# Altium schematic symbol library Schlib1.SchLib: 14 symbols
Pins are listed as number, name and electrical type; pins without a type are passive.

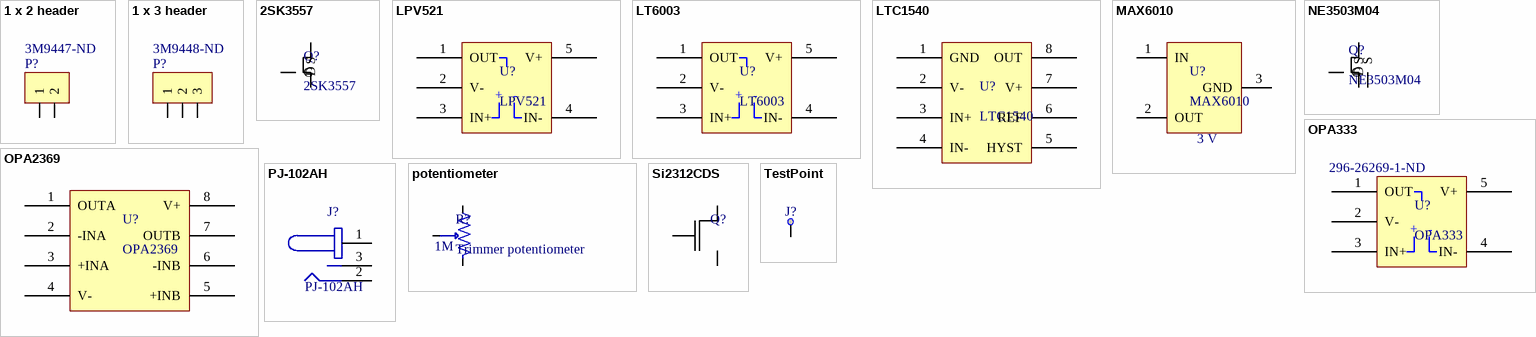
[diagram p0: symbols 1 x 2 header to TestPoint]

## 1 x 2 header
designator P?  Supplier Part Number 1: 3M9447-ND  (hidden comment: 1 x 2 header)
100 mils standard header
footprint 1x2 header (1x2 header, 100 mils)
pins: 1, 2

## 1 x 3 header
designator P?  Supplier Part Number 1: 3M9448-ND  (hidden comment: 1 x 3 header)
100 mils standard header
footprint 1x3 header (1x3 header, 100 mils)
pins: 1, 2, 3

## 2SK3557
designator Q?
N-Channel JFET
footprint SOT23-3N (SOT23, 3-Leads, Body 2.9x1.3mm, Pitch 0.95mm, Lead Span 2.5mm, IPC Medium Density)
pins: 1 S, 2 D, 3 G

## LPV521
designator U?
Nanopower, 1.8V, RRIO, CMOS Input, Operational Amplifier
footprint SC70-5
pins: 1 OUT, 2 V-, 3 IN+, 4 IN-, 5 V+

## LT6003
designator U?
1.6V, 1µA Precision   Rail-to-Rail Input and   Output Op Amps
footprint TSOT23-5 (SOT23, 5-Leads, Body 2.90x2.80mm, Pitch 0.95mm, IPC Medium Density)
pins: 1 OUT, 2 V-, 3 IN+, 4 IN-, 5 V+

## LTC1540
designator U?
Nanopower Comparator  with Reference
footprint SOIC-8 (SOIC, 8-Leads, Body 5.10x3.91mm, Pitch 1.27mm, IPC Medium Density)
pins: 1 GND, 2 V-, 3 IN+, 4 IN-, 5 HYST, 6 REF, 7 V+, 8 OUT

## MAX6010
designator U?  value 3 V
Precision Micropower Shunt Voltage Reference
footprint SOT23-3N (SOT23, 3-Leads, Body 2.9x1.3mm, Pitch 0.95mm, Lead Span 2.5mm, IPC Medium Density)
pins: 1 IN, 2 OUT, 3 GND

## NE3503M04
designator Q?
C TO Ku BAND SUPER LOW NOISE AND HIGH-GAIN AMPLIFIER   N-CHANNEL HJ-FET
footprint M04 (FLAT-LEAD 4-PIN THIN-TYPE SUPER MINIMOLD (M04))
pins: 1 S, 2 D, 3 S, 4 G

## OPA333
designator U?  Supplier Part Number 1: 296-26269-1-ND
1.8V, microPOWER  CMOS OPERATIONAL AMPLIFIERS  Zerø-Drift Series
footprint SOT23-5 (SOT23, 5-Leads, Body 2.9x1.6mm, Pitch 0.95mm, Lead Span 2.8mm, IPC High Density)
pins: 1 OUT, 2 V-, 3 IN+, 4 IN-, 5 V+

## OPA2369
designator U?
1.8V, 700nA, Zerø-Crossover  RAIL-TO-RAIL I/O OPERATIONAL AMPLIFIER
footprint MSOP-8 (TSOP, 8-Leads, Body 3.00x3.00mm, Pitch 0.65mm, IPC Medium Density)
pins: 1 OUTA, 2 -INA, 3 +INA, 4 V-, 5 +INB, 6 -INB, 7 OUTB, 8 V+

## PJ-102AH
designator J?
CONN PWR JACK 2.1X5.5MM HIGH CUR
footprint PJ-102AH (Power Jack)
pins: 1, 2, 3

## potentiometer
designator R?, comment Trimmer potentiometer  value 1M
footprint 3386P (trimming pot)
footprint 3296Y (Bourns 3296Y trimmer)
pins: 1, 2, 3

## Si2312CDS
designator Q?  (value not drawn)
N-Channel 20 V (D-S) MOSFET
footprint SOT23-3N (SOT23, 3-Leads, Body 2.9x1.3mm, Pitch 0.95mm, Lead Span 2.5mm, IPC Medium Density)
pins: 1 G, 2 S, 3 D

## TestPoint
designator J?, comment 5004  (value not drawn)
TEST POINT PC MINI .040"D YELLOW
footprint TestPoint
pins: 1 TB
